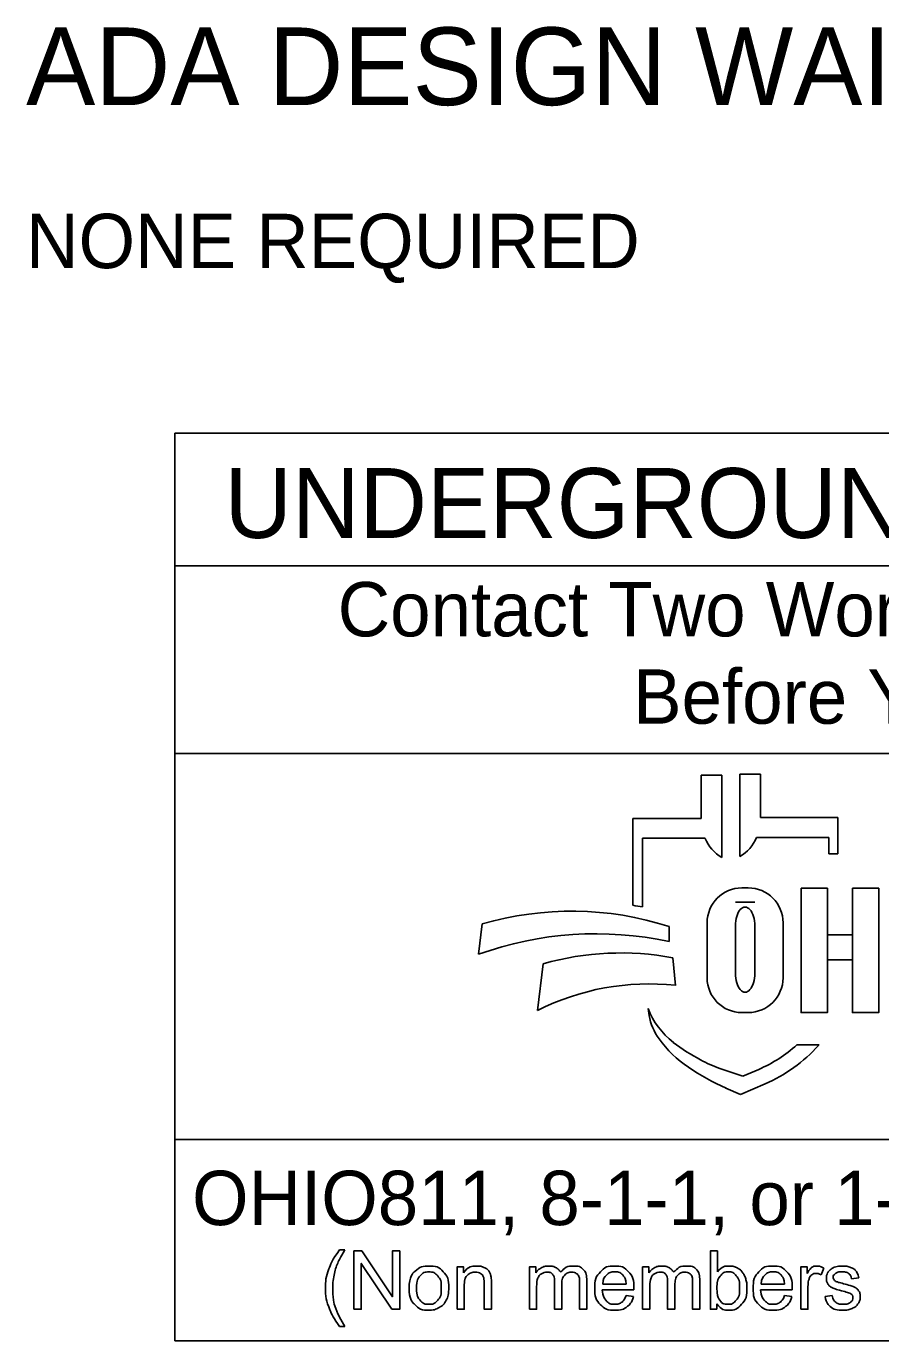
# Model space of a CAD drawing. Extents: x 0 to 34, y -6.8 to 22.
# Drawn here: x 1.995 to 4.196, y 2.143 to 5.529 of the extents above; entities that cross this region are included whole.
import ezdxf

# ---------------------------------------------------------------- set-up
doc = ezdxf.new("R2010")
doc.units = 0
doc.layers.add('GM_X_Minor_Lake', color=7, linetype='Continuous')
doc.layers.add('GM_X_Minor_Lake_Text', color=7, linetype='Continuous')

msp = doc.modelspace()

# ---------------------------------------------------------------- linework, layer by layer
at = {"layer": 'GM_X_Minor_Lake'}
for p, q in [((3.7335, 3.4883), (3.7335, 3.5998)), ((3.7335, 3.5998), (3.7872, 3.5998)), ((3.7872, 3.5998), (3.7872, 3.3877)), ((3.8329, 3.39), (3.8329, 3.6021)), ((3.8329, 3.6021), (3.8865, 3.6021)), ((3.8865, 3.6021), (3.8865, 3.4906)), ((3.5576, 3.2644), (3.5576, 3.4883)), ((3.5576, 3.4883), (3.7335, 3.4883)), ((3.8865, 3.4906), (4.0857, 3.4906)), ((4.0857, 3.4906), (4.0857, 3.3968)), ((3.5828, 3.4369), (3.5828, 3.26)), ((3.7439, 3.4369), (3.5828, 3.4369)), ((4.0625, 3.4392), (3.8761, 3.4392)), ((4.0625, 3.3968), (4.0625, 3.4392)), ((4.0857, 3.3968), (4.0625, 3.3968)), ((3.8385, 3.3091), (3.8551, 3.3091)), ((3.8718, 3.2721), (3.822, 3.2721)), ((3.7491, 3.0776), (3.7491, 3.2196)), ((3.9445, 3.2196), (3.9445, 3.0776)), ((3.1602, 3.1381), (3.1696, 3.2162)), ((3.6509, 3.2097), (3.6509, 3.1709)), ((3.822, 3.089), (3.822, 3.2114)), ((3.8718, 3.2114), (3.8718, 3.089)), ((3.6608, 3.1291), (3.6671, 3.0582)), ((3.312, 2.9936), (3.3267, 3.1137)), ((3.5997, 2.9807), (3.5967, 2.9986)), ((3.8551, 2.9882), (3.8385, 2.9882)), ((3.98, 2.9048), (4.0375, 2.9048)), ((3.7816, 2.8444), (3.841, 2.8239)), ((3.841, 2.8239), (3.8821, 2.8417)), ((3.835, 2.7769), (3.7976, 2.7934)), ((3.8983, 2.8044), (3.835, 2.7769))]:
    msp.add_line(p, q, dxfattribs=at)
for points in [[(3.991, 3.3081), (4.0589, 3.3081), (4.0589, 2.9881), (3.991, 2.9881)], [(4.1231, 3.3081), (4.1911, 3.3081), (4.1911, 2.9881), (4.1231, 2.9881)], [(4.0589, 3.1882), (4.1231, 3.1882), (4.1231, 3.1242), (4.0589, 3.1242)]]:
    msp.add_lwpolyline(points, close=True, dxfattribs=at)
for points in [[(2.8021, 2.3766), (2.8153, 2.3766)], [(2.8389, 2.2239), (2.8389, 2.3741), (2.8592, 2.3741), (2.9382, 2.2561), (2.9382, 2.3741), (2.9572, 2.3741), (2.9572, 2.2239), (2.9369, 2.2239), (2.8579, 2.3419), (2.8579, 2.2239), (2.8389, 2.2239)], [(3.7743, 2.2239), (3.7573, 2.2239), (3.7573, 2.3741), (3.7757, 2.3741), (3.7757, 2.3206)], [(3.1048, 2.2239), (3.1048, 2.3328), (3.1214, 2.3328), (3.1214, 2.3173)], [(3.2912, 2.2239), (3.2912, 2.3328), (3.3077, 2.3328), (3.3077, 2.3174)], [(3.5826, 2.2239), (3.5826, 2.3328), (3.5991, 2.3328), (3.5991, 2.3174)], [(3.9904, 2.2239), (3.9904, 2.3328), (4.007, 2.3328), (4.007, 2.3163)], [(4.0495, 2.3293), (4.043, 2.3122)], [(4.1394, 2.3046), (4.1213, 2.3022)], [(3.1233, 2.2833), (3.1233, 2.2239), (3.1048, 2.2239)], [(3.1932, 2.2908), (3.1932, 2.2239), (3.1748, 2.2239), (3.1748, 2.2901)], [(3.3097, 2.2803), (3.3097, 2.2239), (3.2912, 2.2239)], [(3.3743, 2.2871), (3.3743, 2.2239), (3.3559, 2.2239), (3.3559, 2.2946)], [(3.4388, 2.2986), (3.4388, 2.2239), (3.4203, 2.2239), (3.4203, 2.2924)], [(3.56, 2.2736), (3.4788, 2.2736)], [(3.4799, 2.2887), (3.5406, 2.2887)], [(3.601, 2.2803), (3.601, 2.2239), (3.5826, 2.2239)], [(3.6657, 2.2871), (3.6657, 2.2239), (3.6473, 2.2239), (3.6473, 2.2946)], [(3.7301, 2.2986), (3.7301, 2.2239), (3.7117, 2.2239), (3.7117, 2.2924)], [(3.968, 2.2736), (3.8868, 2.2736)], [(3.8879, 2.2887), (3.9486, 2.2887)], [(4.0088, 2.2809), (4.0088, 2.2239), (3.9904, 2.2239)], [(3.5404, 2.2591), (3.5595, 2.2567)], [(3.7743, 2.2375), (3.7743, 2.2239)], [(3.9484, 2.2591), (3.9675, 2.2567)], [(4.053, 2.2564), (4.0712, 2.2593)], [(2.8153, 2.1798), (2.8021, 2.1798)]]:
    msp.add_lwpolyline(points, dxfattribs=at)
for centre, radius, start, end in [((3.8353, 3.4736), 0.0985, 201.9296, 240.7469), ((3.7847, 3.476), 0.0985, 299.2531, 338.0704), ((3.8385, 3.2196), 0.0895, 90, 180), ((3.8551, 3.2196), 0.0895, 0, 90), ((3.4295, 2.4554), 0.8191, 79.2074, 81.0007), ((3.3997, 2.4302), 0.8191, 72.1402, 106.3144), ((3.4628, 2.2991), 0.8919, 77.8238, 109.8274), ((3.5267, 2.4094), 0.7322, 79.44, 105.8467), ((3.5987, 2.4262), 0.6357, 83.8248, 116.8021), ((3.8385, 3.0776), 0.0895, 180, 270), ((3.8551, 3.0776), 0.0895, 270, 0), ((3.7841, 3.0707), 0.2008, 201.0457, 232.5314), ((3.741, 3.0048), 0.1433, 189.6817, 216.0884), ((3.8747, 3.1022), 0.3088, 216.0884, 235.7167), ((3.9766, 3.3219), 0.5173, 232.5314, 241.794), ((3.7387, 3.1722), 0.3602, 293.4582, 312.0712), ((3.7387, 3.1722), 0.401, 293.4582, 317.8286), ((4.0412, 3.3465), 0.6044, 235.7167, 246.2325), ((3.8914, 3.1631), 0.3371, 241.794, 250.9821)]:
    msp.add_arc(centre, radius, start, end, dxfattribs=at)
for centre, start_param, end_param in [((3.8469, 3.2114), 4.712389, 7.853982), ((3.8469, 3.089), 1.570796, 4.712389)]:
    msp.add_ellipse(centre, major_axis=(0, 0.0484), ratio=0.514403, start_param=start_param, end_param=end_param, dxfattribs=at)
for points in [[(2.8021, 2.1798), (2.7869, 2.199), (2.7763, 2.2248), (2.7657, 2.2506), (2.7657, 2.2783), (2.7657, 2.3026), (2.7736, 2.325), (2.7829, 2.3509), (2.8021, 2.3766)], [(2.8153, 2.3766), (2.8029, 2.3553), (2.7989, 2.3462), (2.7927, 2.332), (2.7891, 2.3167), (2.7847, 2.2975), (2.7847, 2.2782), (2.7847, 2.2289), (2.8153, 2.1798)], [(2.9814, 2.2783), (2.9814, 2.3085), (2.9981, 2.3231), (3.0122, 2.3352), (3.0323, 2.3352), (3.0547, 2.3352), (3.069, 2.3205), (3.0832, 2.3058), (3.0832, 2.2799), (3.0832, 2.2589), (3.0769, 2.2469), (3.0706, 2.2348), (3.0586, 2.2282), (3.0466, 2.2215), (3.0323, 2.2215), (3.0095, 2.2215), (2.9954, 2.2362), (2.9814, 2.2508), (2.9814, 2.2783)], [(3.0003, 2.2783), (3.0003, 2.2574), (3.0094, 2.247), (3.0185, 2.2366), (3.0323, 2.2366), (3.046, 2.2366), (3.0551, 2.2471), (3.0642, 2.2575), (3.0642, 2.279), (3.0642, 2.2991), (3.0551, 2.3095), (3.0459, 2.3199), (3.0323, 2.3199), (3.0185, 2.3199), (3.0094, 2.3096), (3.0003, 2.2992), (3.0003, 2.2783)], [(3.1214, 2.3173), (3.1334, 2.3352), (3.156, 2.3352), (3.1659, 2.3352), (3.1741, 2.3316), (3.1823, 2.3281), (3.1864, 2.3224), (3.1905, 2.3166), (3.1922, 2.3087), (3.1932, 2.3036), (3.1932, 2.2908)], [(3.1748, 2.2901), (3.1748, 2.3013), (3.1726, 2.3069), (3.1705, 2.3125), (3.165, 2.3158), (3.1595, 2.3191), (3.1521, 2.3191), (3.1404, 2.3191), (3.1318, 2.3117), (3.1233, 2.3042), (3.1233, 2.2833)], [(3.3077, 2.3174), (3.3128, 2.3254), (3.3214, 2.3303), (3.3299, 2.3352), (3.3407, 2.3352), (3.3528, 2.3352), (3.3606, 2.3301), (3.3683, 2.3251), (3.3715, 2.3161), (3.3844, 2.3352), (3.4051, 2.3352), (3.4213, 2.3352), (3.43, 2.3262), (3.4388, 2.3172), (3.4388, 2.2986)], [(3.3559, 2.2946), (3.3559, 2.3069), (3.3514, 2.313), (3.3469, 2.3191), (3.3366, 2.3191), (3.3288, 2.3191), (3.3222, 2.315), (3.3156, 2.311), (3.3126, 2.3031), (3.3097, 2.2952), (3.3097, 2.2803)], [(3.4203, 2.2924), (3.4203, 2.3035), (3.4185, 2.3083), (3.4168, 2.3132), (3.412, 2.3162), (3.4073, 2.3191), (3.401, 2.3191), (3.3895, 2.3191), (3.3819, 2.3115), (3.3743, 2.3039), (3.3743, 2.2871)], [(3.5595, 2.2567), (3.555, 2.24), (3.5428, 2.2307), (3.5306, 2.2215), (3.5117, 2.2215), (3.4878, 2.2215), (3.4738, 2.2362), (3.4598, 2.2509), (3.4598, 2.2774), (3.4598, 2.3049), (3.474, 2.32), (3.4881, 2.3352), (3.5106, 2.3352), (3.5324, 2.3352), (3.5463, 2.3203), (3.5601, 2.3055), (3.5601, 2.2785), (3.5601, 2.2769), (3.56, 2.2736)], [(3.5406, 2.2887), (3.5394, 2.3025), (3.5337, 2.3094), (3.5249, 2.3201), (3.5108, 2.3201), (3.4981, 2.3201), (3.4894, 2.3115), (3.4808, 2.303), (3.4799, 2.2887)], [(3.5991, 2.3174), (3.6042, 2.3254), (3.6127, 2.3303), (3.6212, 2.3352), (3.6321, 2.3352), (3.6442, 2.3352), (3.6519, 2.3301), (3.6597, 2.3251), (3.6628, 2.3161), (3.6758, 2.3352), (3.6965, 2.3352), (3.7127, 2.3352), (3.7214, 2.3262), (3.7301, 2.3172), (3.7301, 2.2986)], [(3.6473, 2.2946), (3.6473, 2.3069), (3.6428, 2.313), (3.6383, 2.3191), (3.628, 2.3191), (3.6202, 2.3191), (3.6136, 2.315), (3.607, 2.311), (3.604, 2.3031), (3.601, 2.2952), (3.601, 2.2803)], [(3.7117, 2.2924), (3.7117, 2.3035), (3.7099, 2.3083), (3.7081, 2.3132), (3.7034, 2.3162), (3.6987, 2.3191), (3.6923, 2.3191), (3.6809, 2.3191), (3.6733, 2.3115), (3.6657, 2.3039), (3.6657, 2.2871)], [(3.7741, 2.2792), (3.7741, 2.2596), (3.7794, 2.2509), (3.7881, 2.2366), (3.8029, 2.2366), (3.815, 2.2366), (3.8238, 2.2471), (3.8326, 2.2576), (3.8326, 2.2784), (3.8326, 2.2998), (3.8241, 2.3099), (3.8157, 2.3201), (3.8038, 2.3201), (3.7917, 2.3201), (3.7829, 2.3096), (3.7741, 2.299), (3.7741, 2.2792)], [(3.7757, 2.3206), (3.7874, 2.3352), (3.8055, 2.3352), (3.8155, 2.3352), (3.8245, 2.3311), (3.8335, 2.3271), (3.8392, 2.3198), (3.845, 2.3124), (3.8483, 2.3021), (3.8516, 2.2918), (3.8516, 2.28), (3.8516, 2.252), (3.8378, 2.2368), (3.8239, 2.2215), (3.8046, 2.2215), (3.7853, 2.2215), (3.7743, 2.2375)], [(3.9675, 2.2567), (3.963, 2.24), (3.9508, 2.2307), (3.9386, 2.2215), (3.9196, 2.2215), (3.8958, 2.2215), (3.8818, 2.2362), (3.8678, 2.2509), (3.8678, 2.2774), (3.8678, 2.3049), (3.882, 2.32), (3.8961, 2.3352), (3.9186, 2.3352), (3.9404, 2.3352), (3.9543, 2.3203), (3.9681, 2.3055), (3.9681, 2.2785), (3.9681, 2.2769), (3.968, 2.2736)], [(3.9486, 2.2887), (3.9474, 2.3025), (3.9417, 2.3094), (3.9328, 2.3201), (3.9188, 2.3201), (3.9061, 2.3201), (3.8974, 2.3115), (3.8888, 2.303), (3.8879, 2.2887)], [(4.007, 2.3163), (4.0133, 2.3278), (4.0187, 2.3315), (4.0241, 2.3352), (4.0305, 2.3352), (4.0398, 2.3352), (4.0495, 2.3293)], [(4.043, 2.3122), (4.0363, 2.3162), (4.0295, 2.3162), (4.0235, 2.3162), (4.0187, 2.3125), (4.0139, 2.3089), (4.0119, 2.3024), (4.0088, 2.2926), (4.0088, 2.2809)], [(4.1213, 2.3022), (4.1201, 2.3106), (4.1142, 2.3153), (4.1083, 2.3201), (4.0975, 2.3201), (4.0848, 2.3201), (4.0794, 2.3159), (4.0739, 2.3116), (4.0739, 2.306), (4.0739, 2.3024), (4.0762, 2.2995), (4.0785, 2.2966), (4.0833, 2.2946), (4.086, 2.2936), (4.0996, 2.2899), (4.1192, 2.2847), (4.1269, 2.2813), (4.1347, 2.278), (4.1391, 2.2717), (4.1435, 2.2653), (4.1435, 2.2559), (4.1435, 2.2467), (4.1381, 2.2386), (4.1327, 2.2304), (4.1226, 2.226), (4.1124, 2.2215), (4.0996, 2.2215), (4.0784, 2.2215), (4.0672, 2.2303), (4.0561, 2.2391), (4.053, 2.2564)], [(4.0712, 2.2593), (4.0727, 2.2483), (4.0798, 2.2425), (4.0868, 2.2366), (4.0995, 2.2366), (4.1122, 2.2366), (4.1184, 2.2418), (4.1245, 2.247), (4.1245, 2.254), (4.1245, 2.2602), (4.1191, 2.2638), (4.1153, 2.2663), (4.1002, 2.2701), (4.0799, 2.2752), (4.072, 2.2789), (4.0642, 2.2827), (4.0601, 2.2893), (4.0561, 2.2959), (4.0561, 2.3038), (4.0561, 2.3111), (4.0594, 2.3173), (4.0628, 2.3235), (4.0685, 2.3276), (4.0728, 2.3308), (4.0803, 2.333), (4.0877, 2.3352), (4.0962, 2.3352), (4.109, 2.3352), (4.1187, 2.3315), (4.1284, 2.3278), (4.133, 2.3215), (4.1377, 2.3152), (4.1394, 2.3046)], [(3.4788, 2.2736), (3.4799, 2.2557), (3.489, 2.2462), (3.4981, 2.2366), (3.5117, 2.2366), (3.5219, 2.2366), (3.5291, 2.242), (3.5362, 2.2473), (3.5404, 2.2591)], [(3.8868, 2.2736), (3.8879, 2.2557), (3.897, 2.2462), (3.9061, 2.2366), (3.9197, 2.2366), (3.9299, 2.2366), (3.937, 2.242), (3.9442, 2.2473), (3.9484, 2.2591)]]:
    msp.add_open_spline(points, degree=3, dxfattribs=at)
at = {"layer": 'GM_X_Minor_Lake_Text'}
for p, q in [((2.3775, 2.1428), (2.3775, 4.4803)), ((6.6275, 4.4803), (2.3775, 4.4803)), ((2.3775, 4.1387), (6.6275, 4.1387)), ((2.3775, 3.6553), (6.6275, 3.6553)), ((6.6275, 2.6607), (2.3775, 2.6607)), ((6.6275, 2.1428), (2.3775, 2.1428))]:
    msp.add_line(p, q, dxfattribs=at)

# ---------------------------------------------------------------- texts
at = {"layer": 'GM_X_Minor_Lake'}
for s, height, p in [('ADA DESIGN WAIVERS', 0.2, (1.9944, 5.3256)), ('NONE REQUIRED', 0.14, (1.9944, 4.9056)), ('UNDERGROUND UTILITIES', 0.18, (2.5057, 4.2106)), ('Contact Two Working Days', 0.14, (2.7972, 3.9571)), ('Before You Dig', 0.14, (3.5583, 3.7321)), ('OHIO811, 8-1-1, or 1-800-362-2764', 0.14, (2.422, 2.4406))]:
    msp.add_text(s, height=height, dxfattribs=at).set_placement(p)

doc.saveas('drawing.dxf')
